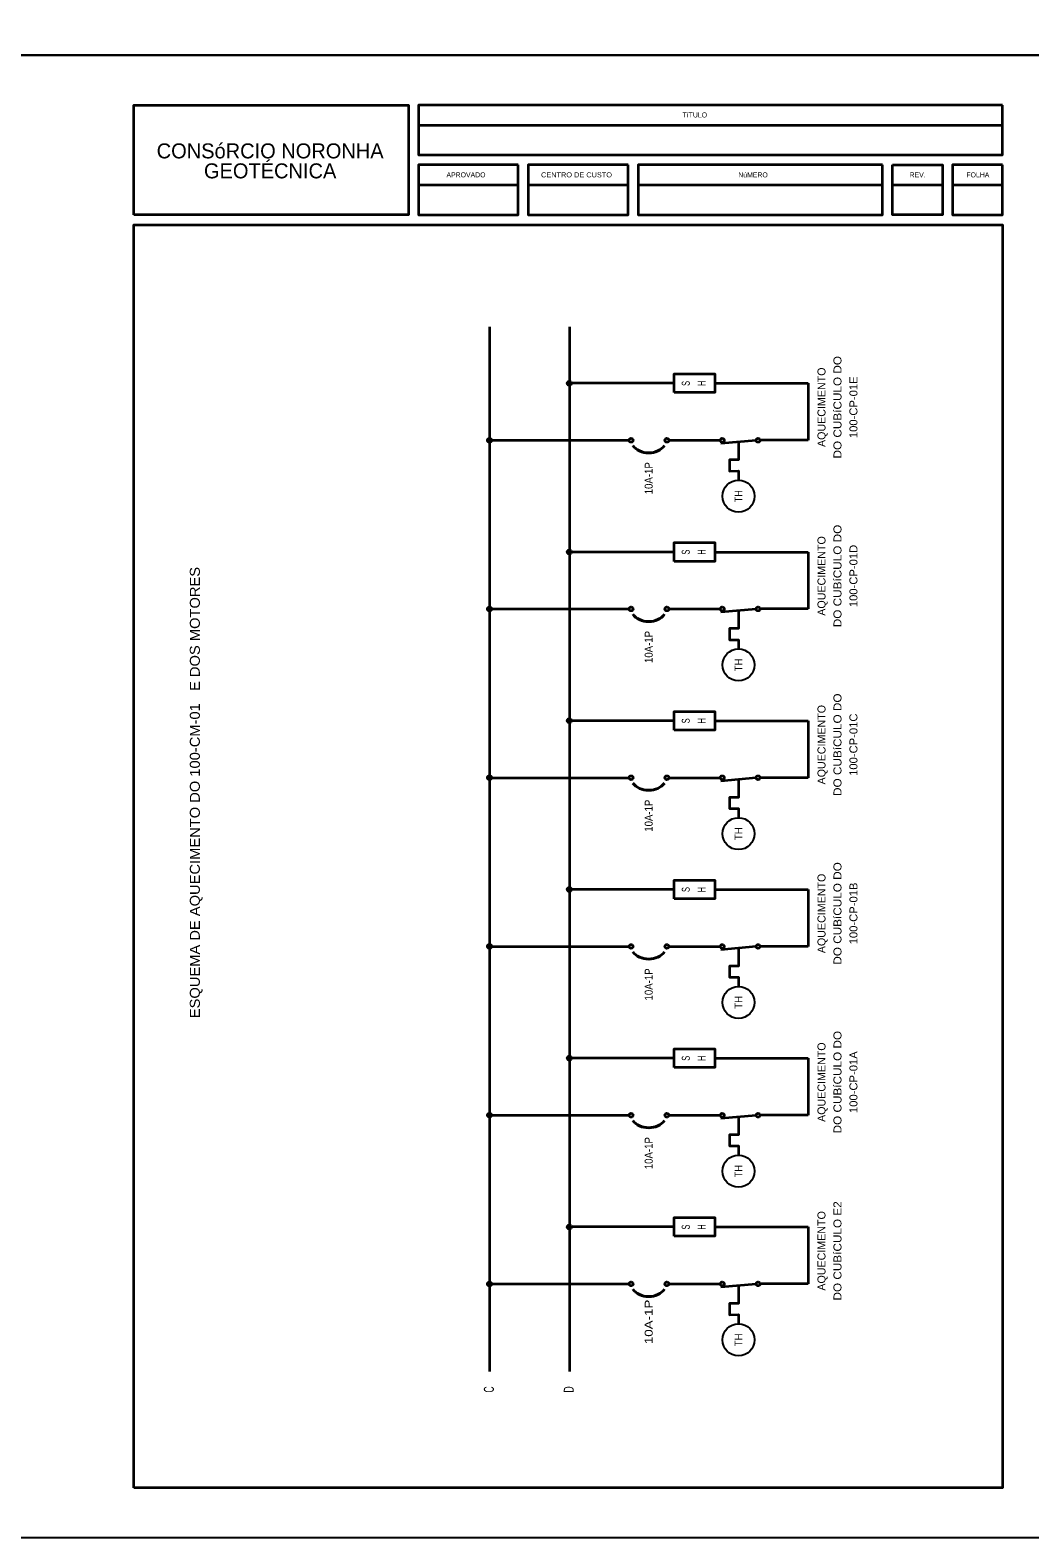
# Model space of a CAD drawing. Extents: x -4160 to -2690, y -474 to 714.
# Drawn here: x -3315.6 to -3115.3, y -473.5 to -171.5 of the extents above; entities that cross this region are included whole.
import ezdxf
from ezdxf.enums import TextEntityAlignment as Align

# ---------------------------------------------------------------- set-up
doc = ezdxf.new("R2010")
doc.units = 0
doc.header["$LTSCALE"] = 0.56
doc.layers.add('2', color=7, linetype='Continuous', lineweight=25)
doc.layers.add('5', color=7, linetype='Continuous', lineweight=35)

msp = doc.modelspace()

# ---------------------------------------------------------------- hatches: boundary and pattern name
at = {"layer": '2'}
for points in [[(-3207.5322, -241.8408, 1), (-3207.5322, -242.6659, 1)], [(-3223.5322, -253.2538, 1), (-3223.5322, -254.079, 1)], [(-3207.5322, -275.6383, 1), (-3207.5322, -276.4634, 1)], [(-3223.5322, -287.0513, 1), (-3223.5322, -287.8765, 1)], [(-3207.5322, -309.4358, 1), (-3207.5322, -310.261, 1)], [(-3223.5322, -320.8488, 1), (-3223.5322, -321.674, 1)], [(-3207.5322, -343.2333, 1), (-3207.5322, -344.0585, 1)], [(-3223.5322, -354.6464, 1), (-3223.5322, -355.4715, 1)], [(-3207.5322, -377.0308, 1), (-3207.5322, -377.856, 1)], [(-3223.5322, -388.4439, 1), (-3223.5322, -389.269, 1)], [(-3207.5322, -410.8284, 1), (-3207.5322, -411.6535, 1)], [(-3223.5322, -422.2414, 1), (-3223.5322, -423.0666, 1)]]:
    msp.add_hatch(color=256, dxfattribs=at).paths.add_polyline_path(points)

# ---------------------------------------------------------------- linework, layer by layer
at = {"layer": '2', "lineweight": 35}
for p, q in [((-3223.5322, -230.9341), (-3223.5322, -440.2276)), ((-3207.5322, -230.9341), (-3207.5322, -440.2276)), ((-3186.5413, -242.2533), (-3207.5322, -242.2533)), ((-3178.357, -242.2533), (-3159.6868, -242.2533)), ((-3159.6868, -242.2533), (-3159.6868, -253.6664)), ((-3223.5322, -253.6664), (-3195.5523, -253.6664)), ((-3187.5902, -253.6664), (-3177.308, -253.6664)), ((-3159.6868, -253.6664), (-3169.3082, -253.6664)), ((-3170.1066, -253.7017), (-3177.1704, -254.3271)), ((-3186.5413, -276.0509), (-3207.5322, -276.0509)), ((-3178.357, -276.0509), (-3159.6868, -276.0509)), ((-3159.6868, -276.0509), (-3159.6868, -287.4639)), ((-3223.5322, -287.4639), (-3195.5523, -287.4639)), ((-3187.5902, -287.4639), (-3177.308, -287.4639)), ((-3170.1066, -287.4992), (-3177.1704, -288.1246)), ((-3159.6868, -287.4639), (-3169.3082, -287.4639)), ((-3186.5413, -309.8484), (-3207.5322, -309.8484)), ((-3178.357, -309.8484), (-3159.6868, -309.8484)), ((-3159.6868, -309.8484), (-3159.6868, -321.2614)), ((-3223.5322, -321.2614), (-3195.5523, -321.2614)), ((-3187.5902, -321.2614), (-3177.308, -321.2614)), ((-3170.1066, -321.2967), (-3177.1704, -321.9221)), ((-3159.6868, -321.2614), (-3169.3082, -321.2614)), ((-3186.5413, -343.6459), (-3207.5322, -343.6459)), ((-3178.357, -343.6459), (-3159.6868, -343.6459)), ((-3159.6868, -343.6459), (-3159.6868, -355.0589)), ((-3223.5322, -355.0589), (-3195.5523, -355.0589)), ((-3187.5902, -355.0589), (-3177.308, -355.0589)), ((-3170.1066, -355.0942), (-3177.1704, -355.7197)), ((-3159.6868, -355.0589), (-3169.3082, -355.0589)), ((-3186.5413, -377.4434), (-3207.5322, -377.4434)), ((-3178.357, -377.4434), (-3159.6868, -377.4434)), ((-3159.6868, -377.4434), (-3159.6868, -388.8565)), ((-3223.5322, -388.8565), (-3195.5523, -388.8565)), ((-3187.5902, -388.8565), (-3177.308, -388.8565)), ((-3170.1066, -388.8917), (-3177.1704, -389.5172)), ((-3159.6868, -388.8565), (-3169.3082, -388.8565)), ((-3186.5413, -411.2409), (-3207.5322, -411.2409)), ((-3178.357, -411.2409), (-3159.6868, -411.2409)), ((-3159.6868, -411.2409), (-3159.6868, -422.654)), ((-3223.5322, -422.654), (-3195.5523, -422.654)), ((-3187.5902, -422.654), (-3177.308, -422.654)), ((-3170.1066, -422.6893), (-3177.1704, -423.3147)), ((-3159.6868, -422.654), (-3169.3082, -422.654))]:
    msp.add_line(p, q, dxfattribs=at)
for points in [[(-3186.5412, -244.1292), (-3186.5412, -240.3776), (-3178.357, -240.3776), (-3178.357, -244.1292)], [(-3186.5412, -277.9267), (-3186.5412, -274.1751), (-3178.357, -274.1751), (-3178.357, -277.9267)], [(-3186.5412, -311.7242), (-3186.5412, -307.9726), (-3178.357, -307.9726), (-3178.357, -311.7242)], [(-3186.5412, -345.5217), (-3186.5412, -341.7701), (-3178.357, -341.7701), (-3178.357, -345.5217)], [(-3186.5412, -379.3193), (-3186.5412, -375.5677), (-3178.357, -375.5677), (-3178.357, -379.3193)], [(-3186.5412, -413.1168), (-3186.5412, -409.3652), (-3178.357, -409.3652), (-3178.357, -413.1168)]]:
    msp.add_lwpolyline(points, close=True, dxfattribs=at)
for points in [[(-3173.6385, -254.0144), (-3173.6385, -257.6081), (-3175.4492, -257.6081), (-3175.4492, -259.8326), (-3173.6385, -259.8212), (-3173.6385, -261.6761)], [(-3173.6385, -287.8119), (-3173.6385, -291.4057), (-3175.4492, -291.4057), (-3175.4492, -293.6301), (-3173.6385, -293.6187), (-3173.6385, -295.4736)], [(-3173.6385, -321.6094), (-3173.6385, -325.2032), (-3175.4492, -325.2032), (-3175.4492, -327.4277), (-3173.6385, -327.4162), (-3173.6385, -329.2711)], [(-3173.6385, -355.4069), (-3173.6385, -359.0007), (-3175.4492, -359.0007), (-3175.4492, -361.2252), (-3173.6385, -361.2137), (-3173.6385, -363.0686)], [(-3173.6385, -389.2045), (-3173.6385, -392.7982), (-3175.4492, -392.7982), (-3175.4492, -395.0227), (-3173.6385, -395.0113), (-3173.6385, -396.8661)], [(-3173.6385, -423.002), (-3173.6385, -426.5957), (-3175.4492, -426.5957), (-3175.4492, -428.8202), (-3173.6385, -428.8088), (-3173.6385, -430.6637)]]:
    msp.add_lwpolyline(points, dxfattribs=at)
for centre, radius in [((-3207.5322, -242.2533), 0.4126), ((-3223.5322, -253.6664), 0.4126), ((-3195.1523, -253.6663), 0.4), ((-3187.9902, -253.6664), 0.4), ((-3176.908, -253.6663), 0.4), ((-3169.7081, -253.6663), 0.4), ((-3207.5322, -276.0509), 0.4126), ((-3223.5322, -287.4639), 0.4126), ((-3195.1523, -287.4639), 0.4), ((-3187.9902, -287.4639), 0.4), ((-3176.908, -287.4639), 0.4), ((-3169.7081, -287.4639), 0.4), ((-3207.5322, -309.8484), 0.4126), ((-3223.5322, -321.2614), 0.4126), ((-3195.1523, -321.2614), 0.4), ((-3187.9902, -321.2615), 0.4), ((-3176.908, -321.2614), 0.4), ((-3169.7081, -321.2614), 0.4), ((-3207.5322, -343.6459), 0.4126), ((-3223.5322, -355.0589), 0.4126), ((-3195.1523, -355.0589), 0.4), ((-3187.9902, -355.059), 0.4), ((-3176.908, -355.0589), 0.4), ((-3169.7081, -355.0589), 0.4), ((-3207.5322, -377.4434), 0.4126), ((-3223.5322, -388.8565), 0.4126), ((-3195.1523, -388.8564), 0.4), ((-3187.9902, -388.8565), 0.4), ((-3176.908, -388.8564), 0.4), ((-3169.7081, -388.8564), 0.4), ((-3207.5322, -411.2409), 0.4126), ((-3223.5322, -422.654), 0.4126), ((-3195.1523, -422.6539), 0.4), ((-3187.9902, -422.654), 0.4), ((-3176.908, -422.6539), 0.4), ((-3169.7081, -422.6539), 0.4)]:
    msp.add_circle(centre, radius, dxfattribs=at)
at = {"layer": '2'}
for centre in [(-3173.6385, -264.8744), (-3173.6385, -298.6719), (-3173.6385, -332.4695), (-3173.6385, -366.267), (-3173.6385, -400.0645), (-3173.6385, -433.862)]:
    msp.add_circle(centre, 3.1984, dxfattribs=at)
at = {"layer": '2', "lineweight": 40}
for centre in [(-3191.6373, -252.9514), (-3191.6373, -286.749), (-3191.6373, -320.5465), (-3191.6373, -354.344), (-3191.6373, -388.1415), (-3191.6373, -421.939)]:
    msp.add_ellipse(centre, major_axis=(-3.8115, 0), ratio=0.85, start_param=0.57974073, end_param=2.56185197, dxfattribs=at)
at = {"layer": '5'}
for p, q in [((-3237.7642, -190.52), (-3120.7642, -190.52)), ((-3237.7642, -202.52), (-3217.7642, -202.52)), ((-3215.7642, -202.52), (-3195.7642, -202.52)), ((-3193.7642, -202.52), (-3144.7642, -202.52)), ((-3142.7642, -202.52), (-3132.7642, -202.52)), ((-3130.7642, -202.52), (-3120.7642, -202.52))]:
    msp.add_line(p, q, dxfattribs=at)
at = {"layer": '5', "lineweight": 25}
for points in [[(-3109.7642, -176.52), (-3319.7642, -176.52), (-3319.7642, 120.48), (-3109.7642, 120.48)], [(-3109.7642, -473.52), (-3319.7642, -473.52), (-3319.7642, -176.52), (-3109.7642, -176.52)]]:
    msp.add_lwpolyline(points, close=True, dxfattribs=at)
at = {"layer": '5'}
for points in [[(-3294.7642, -208.52), (-3294.7642, -186.52), (-3239.7642, -186.52), (-3239.7642, -208.52)], [(-3120.7642, -186.52), (-3237.7642, -186.52), (-3237.7642, -196.52), (-3120.7642, -196.52)], [(-3217.7642, -198.52), (-3237.7642, -198.52), (-3237.7642, -208.52), (-3217.7642, -208.52)], [(-3195.7642, -198.52), (-3215.7642, -198.52), (-3215.7642, -208.52), (-3195.7642, -208.52)], [(-3144.7642, -198.52), (-3193.7642, -198.52), (-3193.7642, -208.52), (-3144.7642, -208.52)], [(-3142.7642, -198.52), (-3132.7642, -198.52), (-3132.7642, -208.52), (-3142.7642, -208.52)], [(-3120.7642, -198.52), (-3130.7642, -198.52), (-3130.7642, -208.52), (-3120.7642, -208.52)], [(-3294.7642, -463.52), (-3294.7642, -210.52), (-3120.7642, -210.52), (-3120.7642, -463.52)]]:
    msp.add_lwpolyline(points, close=True, dxfattribs=at)

# ---------------------------------------------------------------- texts
at = {"layer": '2'}
for s, height, width, p in [('DO CUBíCULO DO', 1.6, 1.1, (-3153.0102, -247.0542)), ('100-CP-01E', 1.6, 1.05, (-3149.8102, -247.0542)), ('S', 1.6, 0.7, (-3183.4063, -242.2717)), ('H', 1.6, 0.6, (-3180.2063, -242.2717)), ('10A-1P', 1.6, 0.9, (-3190.8333, -261.2748)), ('TH', 1.6, 0.85, (-3172.8386, -264.8745)), ('DO CUBíCULO DO', 1.6, 1.1, (-3153.0102, -280.8518)), ('100-CP-01D', 1.6, 1.05, (-3149.8102, -280.8517)), ('S', 1.6, 0.7, (-3183.4063, -276.0681)), ('H', 1.6, 0.6, (-3180.2063, -276.0698)), ('ESQUEMA DE AQUECIMENTO DO 100-CM-01   E DOS MOTORES', 2, 1.1, (-3281.5647, -324.2357)), ('10A-1P', 1.6, 0.9, (-3190.8333, -295.0724)), ('TH', 1.6, 0.9, (-3172.8386, -298.672)), ('DO CUBíCULO DO', 1.6, 1.1, (-3153.0102, -314.6493)), ('S', 1.6, 0.7, (-3183.4063, -309.8656)), ('H', 1.6, 0.6, (-3180.2063, -309.8673)), ('100-CP-01C', 1.6, 1.05, (-3149.8102, -314.6493)), ('10A-1P', 1.6, 0.9, (-3190.8333, -328.8699)), ('TH', 1.6, 0.9, (-3172.8386, -332.4695)), ('DO CUBíCULO DO', 1.6, 1.1, (-3153.0102, -348.4468)), ('S', 1.6, 0.7, (-3183.4063, -343.6631)), ('H', 1.6, 0.6, (-3180.2063, -343.6648)), ('100-CP-01B', 1.6, 1.05, (-3149.8102, -348.4468)), ('10A-1P', 1.6, 0.9, (-3190.8333, -362.6674)), ('TH', 1.6, 0.9, (-3172.8386, -366.2671)), ('DO CUBíCULO DO', 1.6, 1.1, (-3153.0102, -382.2443)), ('S', 1.6, 0.7, (-3183.4063, -377.4606)), ('H', 1.6, 0.6, (-3180.2063, -377.4624)), ('100-CP-01A', 1.6, 1.05, (-3149.8102, -382.2443)), ('10A-1P', 1.6, 0.9, (-3190.8333, -396.4649)), ('TH', 1.6, 0.85, (-3172.8386, -400.0645)), ('DO CUBíCULO E2', 1.6, 1.1, (-3153.0122, -416.0418)), ('S', 1.6, 0.7, (-3183.4063, -411.2582)), ('H', 1.6, 0.6, (-3180.2063, -411.2599)), ('10A-1P', 1.6, 1.25, (-3190.8333, -430.2625)), ('TH', 1.6, 0.9, (-3172.8386, -433.8621)), ('C', 2, 0.65, (-3222.6525, -443.798)), ('D', 2, 0.65, (-3206.6525, -443.798))]:
    msp.add_text(s, height=height, rotation=90, dxfattribs=dict(at, width=width)).set_placement(p, align=Align.CENTER)
for p in [(-3156.2102, -247.0542), (-3156.2102, -280.8517), (-3156.2102, -314.6492), (-3156.2102, -348.4467), (-3156.2102, -382.2442), (-3156.2122, -416.0418)]:
    msp.add_text('AQUECIMENTO', height=1.6, rotation=90, dxfattribs=at).set_placement(p, align=Align.CENTER)
at = {"layer": '5'}
for s, height, p in [('TíTULO', 1, (-3182.3847, -189.009)), ('CONSóRCIO NORONHA', 3, (-3267.4749, -197.2039)), ('GEOTÉCNICA', 3, (-3267.475, -201.2039)), ('APROVADO', 1, (-3228.2387, -201.0027)), ('REV.', 1, (-3137.7443, -201.0077)), ('FOLHA', 1, (-3125.6809, -201.0077))]:
    msp.add_text(s, height=height, dxfattribs=at).set_placement(p, align=Align.CENTER)
for s, width, p in [('CENTRO DE CUSTO', 1.1, (-3206.0934, -201.0027)), ('NúMERO', 0.95, (-3170.7228, -201.0077))]:
    msp.add_text(s, height=1, dxfattribs=dict(at, width=width)).set_placement(p, align=Align.CENTER)

doc.saveas('drawing.dxf')
